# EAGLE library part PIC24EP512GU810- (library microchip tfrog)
PIC24EPXXXGU810/PF High-Performance, 16-bit Digital Signal Controllers and Microcontrollers PIC24EP512GU810-E/PF PIC24EP512GU810-I/PF PIC24EP512GU810T-E/PF PIC24EP512GU810T-I/PF PF=14x14x1mm Microchip pages: http://www.microchip.com/wwwproducts/Devices.aspx?dDocName=en554334 Datasheet: http://ww1.microchip.com/downloads/en/DeviceDoc/70616E.pdf 3V to 3.6V, 512KB+24KB internal flash, RAM 50KB, ADC 12bits x 32, USB otg, 60MIPS/7.37Mhz internal osc. Microchip?s PIC24E general purpose microcontroller family features the highest speed 60 MIPS core with excellent performance and code density. It offers superior ADC performance, enhanced CAN communication, easier graphic display interface through 8-bit parallel master port and up to 15 DMA channels for extensive data movement. These devices are available in various packages and with extended (125°C) temp option. Divers: Batteries charge: http://www.microchip.com/wwwproducts/Devices.aspx?dDocName=en543956
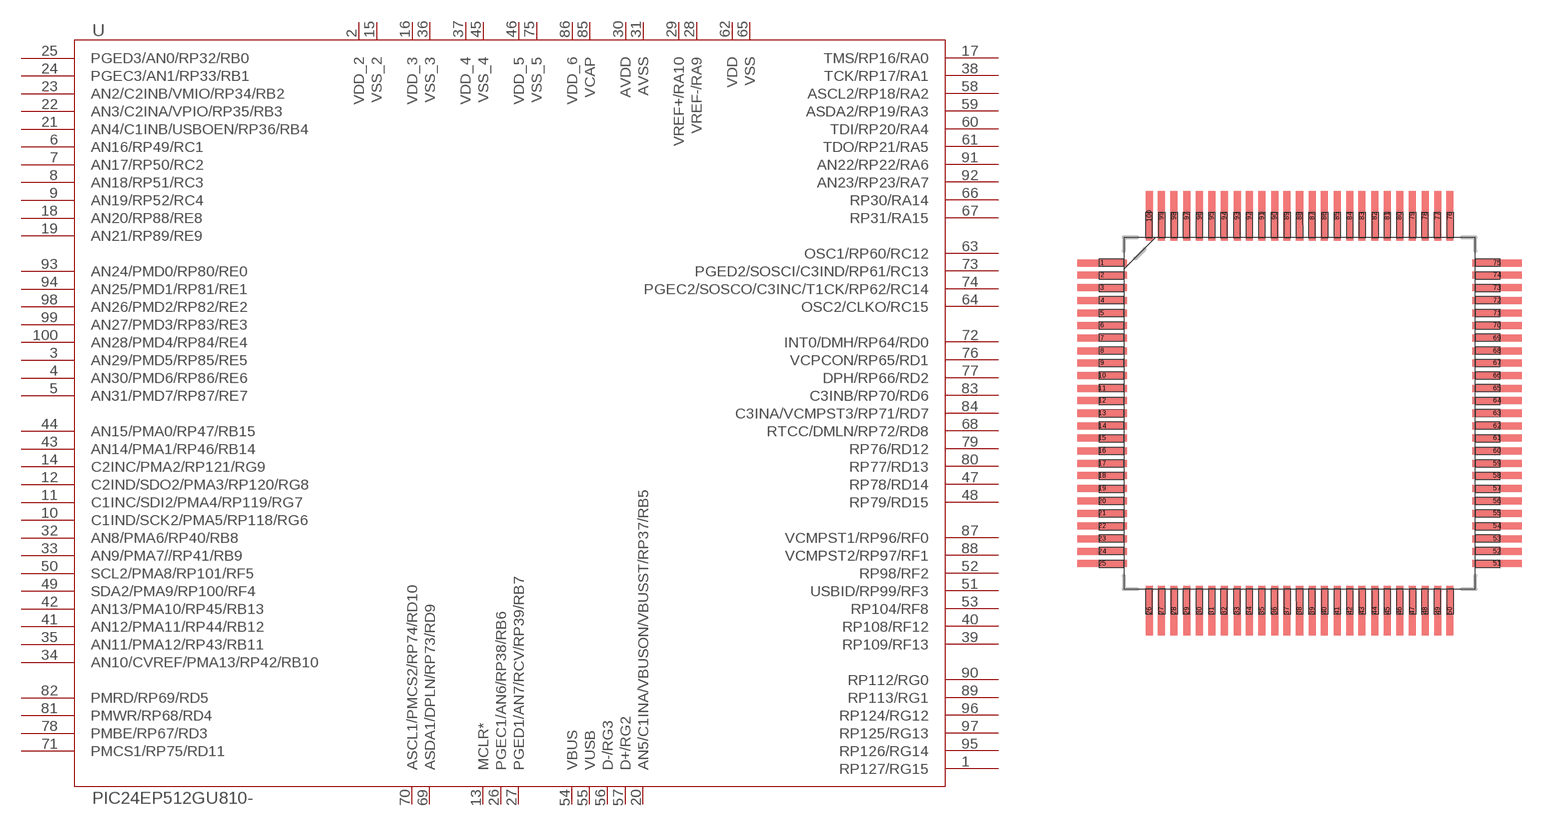
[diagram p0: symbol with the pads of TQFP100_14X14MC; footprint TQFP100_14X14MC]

Designator prefix -

## PIC24EP512GU810-  [TQFP100_14X14MC]
1  RP127/RG15  pas
2  VDD_2  pas
3  AN29/PMD5/RP85/RE5  pas
4  AN30/PMD6/RP86/RE6  pas
5  AN31/PMD7/RP87/RE7  pas
6  AN16/RP49/RC1  pas
7  AN17/RP50/RC2  pas
8  AN18/RP51/RC3  pas
9  AN19/RP52/RC4  pas
10  C1IND/SCK2/PMA5/RP118/RG6  pas
11  C1INC/SDI2/PMA4/RP119/RG7  pas
12  C2IND/SDO2/PMA3/RP120/RG8  pas
13  MCLR*  pas
14  C2INC/PMA2/RP121/RG9  pas
15  VSS_2  pas
16  VDD_3  pas
17  TMS/RP16/RA0  pas
18  AN20/RP88/RE8  pas
19  AN21/RP89/RE9  pas
20  AN5/C1INA/VBUSON/VBUSST/RP37/RB5  pas
21  AN4/C1INB/USBOEN/RP36/RB4  pas
22  AN3/C2INA/VPIO/RP35/RB3  pas
23  AN2/C2INB/VMIO/RP34/RB2  pas
24  PGEC3/AN1/RP33/RB1  pas
25  PGED3/AN0/RP32/RB0  pas
26  PGEC1/AN6/RP38/RB6  pas
27  PGED1/AN7/RCV/RP39/RB7  pas
28  VREF-/RA9  pas
29  VREF+/RA10  pas
30  AVDD  pas
31  AVSS  pas
32  AN8/PMA6/RP40/RB8  pas
33  AN9/PMA7//RP41/RB9  pas
34  AN10/CVREF/PMA13/RP42/RB10  pas
35  AN11/PMA12/RP43/RB11  pas
36  VSS_3  pas
37  VDD_4  pas
38  TCK/RP17/RA1  pas
39  RP109/RF13  pas
40  RP108/RF12  pas
41  AN12/PMA11/RP44/RB12  pas
42  AN13/PMA10/RP45/RB13  pas
43  AN14/PMA1/RP46/RB14  pas
44  AN15/PMA0/RP47/RB15  pas
45  VSS_4  pas
46  VDD_5  pas
47  RP78/RD14  pas
48  RP79/RD15  pas
49  SDA2/PMA9/RP100/RF4  pas
50  SCL2/PMA8/RP101/RF5  pas
51  USBID/RP99/RF3  pas
52  RP98/RF2  pas
53  RP104/RF8  pas
54  VBUS  pas
55  VUSB  pas
56  D-/RG3  pas
57  D+/RG2  pas
58  ASCL2/RP18/RA2  pas
59  ASDA2/RP19/RA3  pas
60  TDI/RP20/RA4  pas
61  TDO/RP21/RA5  pas
62  VDD  pas
63  OSC1/RP60/RC12  pas
64  OSC2/CLKO/RC15  pas
65  VSS  pas
66  RP30/RA14  pas
67  RP31/RA15  pas
68  RTCC/DMLN/RP72/RD8  pas
69  ASDA1/DPLN/RP73/RD9  pas
70  ASCL1/PMCS2/RP74/RD10  pas
71  PMCS1/RP75/RD11  pas
72  INT0/DMH/RP64/RD0  pas
73  PGED2/SOSCI/C3IND/RP61/RC13  pas
74  PGEC2/SOSCO/C3INC/T1CK/RP62/RC14  pas
75  VSS_5  pas
76  VCPCON/RP65/RD1  pas
77  DPH/RP66/RD2  pas
78  PMBE/RP67/RD3  pas
79  RP76/RD12  pas
80  RP77/RD13  pas
81  PMWR/RP68/RD4  pas
82  PMRD/RP69/RD5  pas
83  C3INB/RP70/RD6  pas
84  C3INA/VCMPST3/RP71/RD7  pas
85  VCAP  pas
86  VDD_6  pas
87  VCMPST1/RP96/RF0  pas
88  VCMPST2/RP97/RF1  pas
89  RP113/RG1  pas
90  RP112/RG0  pas
91  AN22/RP22/RA6  pas
92  AN23/RP23/RA7  pas
93  AN24/PMD0/RP80/RE0  pas
94  AN25/PMD1/RP81/RE1  pas
95  RP126/RG14  pas
96  RP124/RG12  pas
97  RP125/RG13  pas
98  AN26/PMD2/RP82/RE2  pas
99  AN27/PMD3/RP83/RE3  pas
100  AN28/PMD4/RP84/RE4  pas

## Footprint TQFP100_14X14MC (pad centres in mm)
TQFP100 with long pads (0.08inch instead of 0.06)
smd 1.981 x 0.279: 1 -7.874,5.994; 2 -7.874,5.512; 3 -7.874,5.004; 4 -7.874,4.496; 5 -7.874,3.988; 6 -7.874,3.505; 7 -7.874,2.997; 8 -7.874,2.489; 9 -7.874,2.007; 10 -7.874,1.499; 11 -7.874,0.991; 12 -7.874,0.508; 13 -7.874,0; 14 -7.874,-0.508; 15 -7.874,-0.991; 16 -7.874,-1.499; 17 -7.874,-2.007; 18 -7.874,-2.489; 19 -7.874,-2.997; 20 -7.874,-3.505; 21 -7.874,-3.988; 22 -7.874,-4.496; 23 -7.874,-5.004; 24 -7.874,-5.512; 25 -7.874,-5.994; 51 7.874,-5.994; 52 7.874,-5.512; 53 7.874,-5.004; 54 7.874,-4.496; 55 7.874,-3.988; 56 7.874,-3.505; 57 7.874,-2.997; 58 7.874,-2.489; 59 7.874,-2.007; 60 7.874,-1.499; 61 7.874,-0.991; 62 7.874,-0.508; 63 7.874,0; 64 7.874,0.508; 65 7.874,0.991; 66 7.874,1.499; 67 7.874,2.007; 68 7.874,2.489; 69 7.874,2.997; 70 7.874,3.505; 71 7.874,3.988; 72 7.874,4.496; 73 7.874,5.004; 74 7.874,5.512; 75 7.874,5.994
smd 0.279 x 1.981: 26 -5.994,-7.874; 27 -5.512,-7.874; 28 -5.004,-7.874; 29 -4.496,-7.874; 30 -3.988,-7.874; 31 -3.505,-7.874; 32 -2.997,-7.874; 33 -2.489,-7.874; 34 -2.007,-7.874; 35 -1.499,-7.874; 36 -0.991,-7.874; 37 -0.508,-7.874; 38 0,-7.874; 39 0.508,-7.874; 40 0.991,-7.874; 41 1.499,-7.874; 42 2.007,-7.874; 43 2.489,-7.874; 44 2.997,-7.874; 45 3.505,-7.874; 46 3.988,-7.874; 47 4.496,-7.874; 48 5.004,-7.874; 49 5.512,-7.874; 50 5.994,-7.874; 76 5.994,7.874; 77 5.512,7.874; 78 5.004,7.874; 79 4.496,7.874; 80 3.988,7.874; 81 3.505,7.874; 82 2.997,7.874; 83 2.489,7.874; 84 2.007,7.874; 85 1.499,7.874; 86 0.991,7.874; 87 0.508,7.874; 88 0,7.874; 89 -0.508,7.874; 90 -0.991,7.874; 91 -1.499,7.874; 92 -2.007,7.874; 93 -2.489,7.874; 94 -2.997,7.874; 95 -3.505,7.874; 96 -3.988,7.874; 97 -4.496,7.874; 98 -5.004,7.874; 99 -5.512,7.874; 100 -5.994,7.874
